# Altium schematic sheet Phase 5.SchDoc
size Tabloid; SheetNumber: 7; SheetTotal: 7
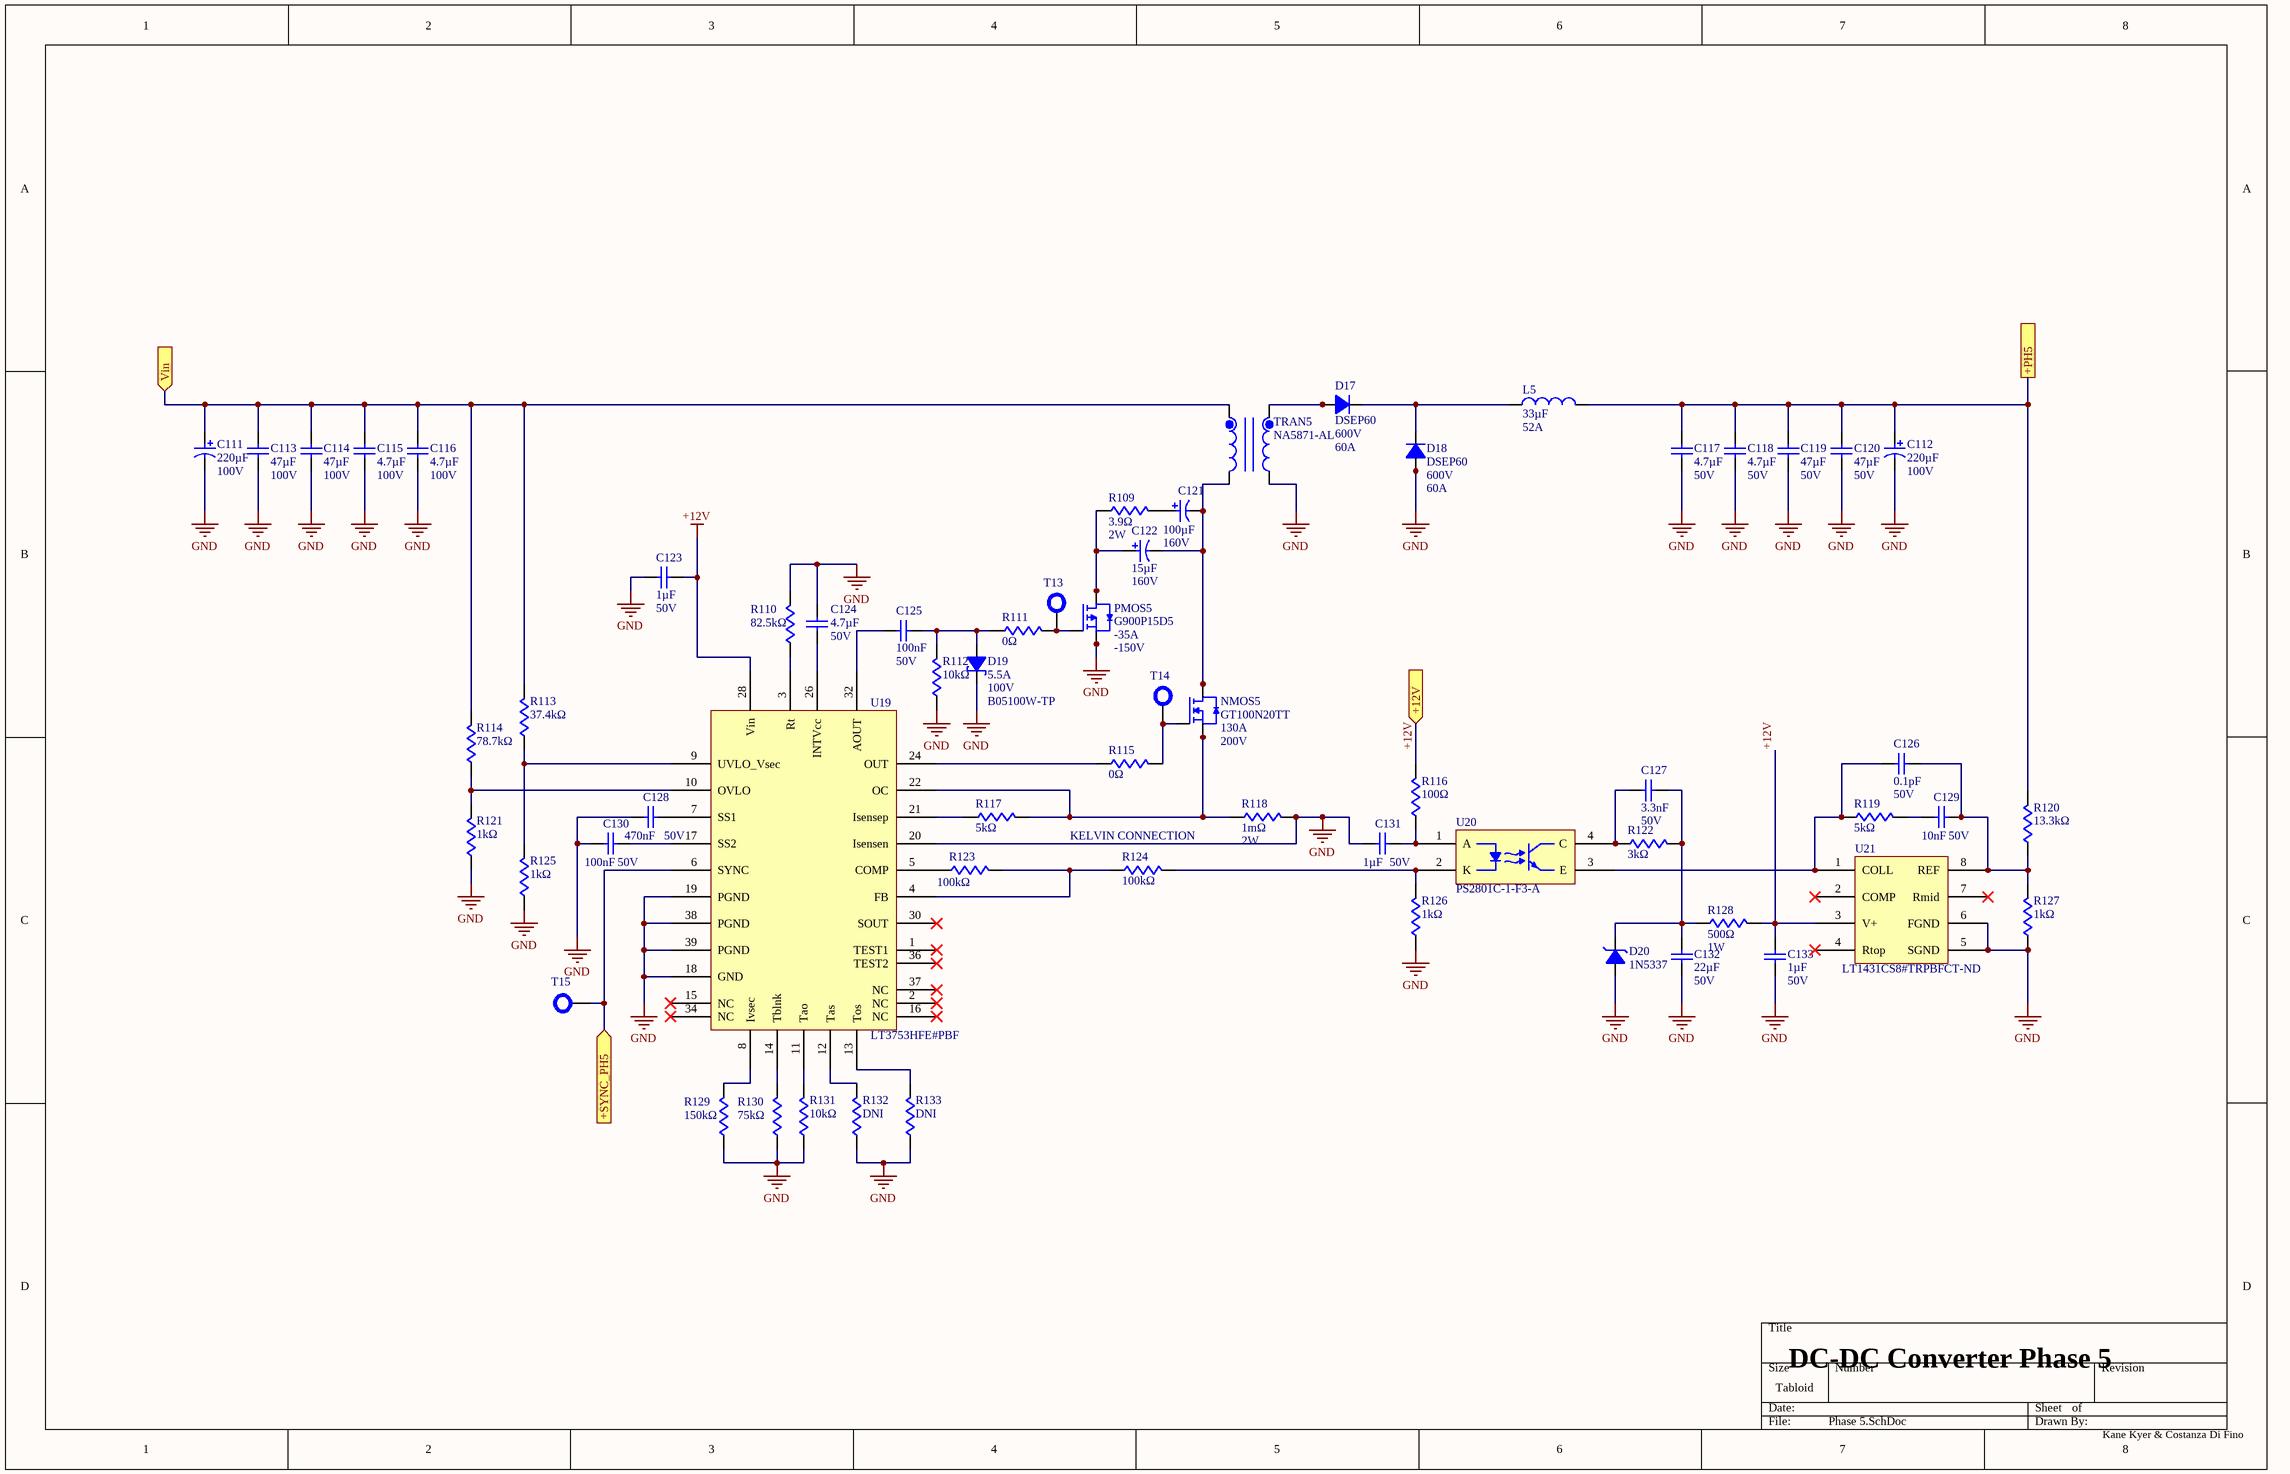
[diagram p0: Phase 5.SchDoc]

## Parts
C111  value 220µF  Voltage Rating: 100V  [C_AEC]  (hidden comment: AFK227M2AR44T-F)
C112  value 220µF  Voltage Rating: 100V  [C_AEC]  (hidden comment: AFK227M2AR44T-F)
C113  value 47µF  Voltage Rating: 100V  [C_CAA573]  (hidden comment: CAA573X7S2A476M640LH)
C114  value 47µF  Voltage Rating: 100V  [C_CAA573]  (hidden comment: CAA573X7S2A476M640LH)
C115  value 4.7µF  Voltage Rating (DC): 100V  [C_1210]  (hidden comment: GMC32X7S475K100NT)
C116  value 4.7µF  Voltage Rating (DC): 100V  [C_1210]  (hidden comment: GMC32X7S475K100NT)
C117  value 4.7µF  Voltage Rating (DC): 50V  [C_1206]  (hidden comment: GMC31X7R475K50NT)
C118  value 4.7µF  Voltage Rating (DC): 50V  [C_1206]  (hidden comment: GMC31X7R475K50NT)
C119  value 47µF  Voltage Rating (DC): 50V  [C_CKG57N]  (hidden comment: CKG57NX7R1H476M500JJ)
C120  value 47µF  Voltage Rating (DC): 50V  [C_CKG57N]  (hidden comment: CKG57NX7R1H476M500JJ)
C121  value 100µF  Voltage Rating (DC): 160V  [UUJ2C101MNJ1MS]  (hidden comment: UUJ2C101MNJ1MS)
C122  value 15µF  Voltage: 160V  [ULT2C150MNL1GS]  (hidden comment: ULT2C150MNL1GS)
C123  value 1µF  Voltage: 50V  [C_0805]  (hidden comment: CL21B105KBFNNNE)
C124  value 4.7µF  Voltage Rating (DC): 50V  [C_1206]  (hidden comment: GMC31X7R475K50NT)
C125  value 100nF  Voltage Rating: 50V  [C_0603]  (hidden comment: C0603C104K5RACTU)
C126  value 0.1pF  Voltage Rating: 50V  [C_0402]  (hidden comment: GJM1555C1HR10WB01D)
C127  value 3.3nF  Voltage Rating: 50V  [C_0603]  (hidden comment: GCM1885C1H332FA16D)
C128  value 470nF  Voltage Rating: 50V  [C_0402]  (hidden comment: GRM155R61H474KE11D)
C129  value 10nF  Voltage Rating: 50V  [C_0603]  (hidden comment: C0603C103K5RACTU)
C130  value 100nF  Voltage Rating: 50V  [C_0603]  (hidden comment: C0603C104K5RACTU)
C131  value 1µF  Voltage: 50V  [C_0805]  (hidden comment: CL21B105KBFNNNE)
C132  value 22µF  Voltage Rating (DC): 50V  [C_2220]  (hidden comment: GMC55X7R226M50NT)
C133  value 1µF  Voltage: 50V  [C_0805]  (hidden comment: CL21B105KBFNNNE)
D17  DSEP60  Vr: 600V  Io: 60A  [D_DSEP60]
D18  DSEP60  Vr: 600V  Io: 60A  [D_DSEP60]
D19  Max Forward Surge Current (Ifsm): 5.5A  Min Breakdown Voltage: 100V  [D_B05100W]  (hidden comment: B05100W-TP)
D20  Supplier Part Number: 1N5337  [D_1N5337]  (hidden comment: 1N5337BRLG)
L5  value 33µF  Irms: 52A  [CPEX4141L-330MC]  (hidden comment: CPEX4141L-330MC)
NMOS5  Id: 130A  Vds: 200V  [GT100N20TT]  (hidden comment: GT100N20TT)
PMOS5  Id: -35A  Vds: -150V  [G900P15]  (hidden comment: G900P15D5)
R109  value 3.9Ω  Power Rating: 2W  [R_SM2W]  (hidden comment: SMW23R9JT)
R110  value 82.5kΩ  [R_0805]  (hidden comment: RMCF0805FT82K5)
R111  value 0Ω  [R_0805]  (hidden comment: CRCW08050000Z0EA)
R112  value 10kΩ  [R_0402]  (hidden comment: RM04F1002CT)
R113  value 37.4kΩ  [R_0603]  (hidden comment: RC0603FR-0737K4L)
R114  value 78.7kΩ  [R_0603]  (hidden comment: RC0603FR-0778K7L)
R115  value 0Ω  [R_0805]  (hidden comment: CRCW08050000Z0EA)
R116  value 100Ω  [R_0603]  (hidden comment: RC0603FR-07100RL)
R117  value 5kΩ  [R_0402]  (hidden comment: PNM0402E5001BST1)
R118  value 1mΩ  Power Rating: 2W  [R_2512]  (hidden comment: CRE2512-FZ-R001E-2)
R119  value 5kΩ  [R_0402]  (hidden comment: PNM0402E5001BST1)
R120  value 13.3kΩ  [R_0603]  (hidden comment: RMCF0603FT13K3)
R121  value 1kΩ  [R_0402]  (hidden comment: RM04F1001CT)
R122  value 3kΩ  [C_0402]  (hidden comment: AC0402FR-073KL)
R123  value 100kΩ  [R_0402]  (hidden comment: RM04F1003CT)
R124  value 100kΩ  [R_0402]  (hidden comment: RM04F1003CT)
R125  value 1kΩ  [R_0402]  (hidden comment: RM04F1001CT)
R126  value 1kΩ  [R_0402]  (hidden comment: RM04F1001CT)
R127  value 1kΩ  [R_0402]  (hidden comment: RM04F1001CT)
R128  value 500Ω  Power Rating: 1W  [R_WSC2515]  (hidden comment: WSC2515500R0FEB)
R129  value 150kΩ  [R_0603]  (hidden comment: RC0603FR-07150KL)
R130  value 75kΩ  [R_0603]  (hidden comment: AC0603FR-0775KL)
R131  value 10kΩ  [R_0402]  (hidden comment: RM04F1002CT)
R132  value DNI  [R_0805]  (hidden comment: CRCW08050000Z0EA)
R133  value DNI  [R_0805]  (hidden comment: CRCW08050000Z0EA)
T13  TEST  [TEST_POINT]  (value not drawn)
T14  TEST  [TEST_POINT]  (value not drawn)
T15  TEST  [TEST_POINT]  (value not drawn)
TRAN5  NA5871-AL  [NA5871-AL]
U19  LT3753HFE#PBF  [LT3753]
U20  PS2801C-1-F3-A  [PS2801C]
U21  Supplier Part Number: LT1431CS8#TRPBFCT-ND  [LT1431]  (hidden comment: LT1431CS8#TRPBF)

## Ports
+12V (in, see SHEET_MAP[4C], Externals[2A], Phase 1[4C], Phase 2[4C], Phase 3[4C], Phase 4[4C]), +PH5 (see SHEET_MAP[4C], Externals[6C], Phase 4[6C]), +SYNC_PH5 (in, see SHEET_MAP[4C], Externals[3C]), Vin (in, see SHEET_MAP[4C], Externals[1A], Phase 1[1B], Phase 2[1B], Phase 3[1B], Phase 4[1B])

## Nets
+12V: C123.2 C133.2 R116.2 R128.2 U19.28(Vin) U21.3(V+) ; port +12V
GND: C111.2 C112.2 C113.1 C114.1 C115.1 C116.1 C117.1 C118.1 C119.1 C120.1 C123.1 C124.1 C128.1 C130.1 C131.1 C132.1 C133.1 D18.1(A) D18.3(A) D19.1 D20.2 PMOS5.1(S) PMOS5.2(S) PMOS5.3(S) R110.2 R112.1 R118.2 R121.1 R125.1 R126.1 R127.1 R129.1 R130.1 R131.1 R132.1 R133.1 TRAN5.11 U19.18(GND) U19.19(PGND) U19.20(Isensen) U19.38(PGND) U19.39(PGND) U21.5(SGND) U21.6(FGND)
+PH5: C112.1 C117.2 C118.2 C119.2 C120.2 L5.2 R120.2 ; port +PH5
+SYNC_PH5: T15.1 U19.6(SYNC) ; port +SYNC_PH5
Vin: C111.1 C113.2 C114.2 C115.2 C116.2 R113.2 R114.2 TRAN5.1 ; port Vin
NetC121_1: C121.1 R109.2
NetC121_2: C121.2 C122.2 NMOS5.9(D) NMOS5.10(D) NMOS5.11(D) NMOS5.12(D) NMOS5.13(D) NMOS5.14(D) NMOS5.15(D) NMOS5.16(D) TRAN5.4
NetC122_1: C122.1 PMOS5.5(D) PMOS5.6(D) PMOS5.7(D) PMOS5.8(D) R109.1
NetC124_2: C124.2 U19.26(INTVcc)
NetC125_1: C125.1 U19.32(AOUT)
NetC125_2: C125.2 D19.2 R111.1 R112.2
NetC126_1: C126.1 R119.1 U20.3(E) U21.1(COLL)
NetC126_2: C126.2 C129.2 R120.1 R127.2 U21.8(REF)
NetC127_1: C127.1 R122.1 U20.4(C)
NetC127_2: C127.2 C132.2 D20.1 R122.2 R128.1
NetC128_2: C128.2 U19.7(SS1)
NetC129_1: C129.1 R119.2
NetC130_2: C130.2 U19.17(SS2)
NetC131_2: C131.2 R116.1 U20.1(A)
NetD17_1: D17.1(A) D17.3(A) TRAN5.6
NetD17_4: D17.4(C) D18.4(C) L5.1
NetNMOS5_1: NMOS5.1(S) NMOS5.2(S) NMOS5.3(S) NMOS5.4(S) NMOS5.5(S) NMOS5.6(S) NMOS5.7(S) R117.2 R118.1 U19.22(OC)
NetNMOS5_8: NMOS5.8(G) R115.2 T14.1
NetPMOS5_4: PMOS5.4(G) R111.2 T13.1
NetR110_1: R110.1 U19.3(Rt)
NetR113_1: R113.1 R125.2 U19.9(UVLO_Vsec)
NetR114_1: R114.1 R121.2 U19.10(OVLO)
NetR115_1: R115.1 U19.24(OUT)
NetR117_1: R117.1 U19.21(Isensep)
NetR123_1: R123.1 U19.5(COMP)
NetR123_2: R123.2 R124.1 U19.4(FB)
NetR124_2: R124.2 R126.2 U20.2(K)
NetR129_2: R129.2 U19.8(Ivsec)
NetR130_2: R130.2 U19.14(Tblnk)
NetR131_2: R131.2 U19.11(Tao)
NetR132_2: R132.2 U19.12(Tas)
NetR133_2: R133.2 U19.13(Tos)

Not connected (* = marked no-connect by the designer): U19 1(TEST1)* 2(NC)* 15(NC)* 16(NC)* 30(SOUT)* 34(NC)* 36(TEST2)* 37(NC)*; U21 2(COMP)* 4(Rtop)* 7(Rmid)*

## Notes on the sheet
- (near R124) KELVIN CONNECTION
- DC-DC Converter Phase 5
- Kane Kyer & Costanza Di Fino

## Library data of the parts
C111 C112 = AFK227M2AR44T-F: Radial Can - SMD ALUMINUM ELECTROLYTIC CAPACITOR AFK 100V 220muF ±20% 0.709Dia 18.00mm; Manufacturer: Cornell Dubilier; Dissipation Factor: 0.07%; ESR (Equivalent Series Resistance): 150mΩ; Leakage Current: 220µA; Life (Hours): 5000hours; Ripple Current: 687.75mA; Ripple Current (AC): 917mA
C113 C114 = CAA573X7S2A476M640LH: Multilayer Ceramic Chip Capacitors, Capacitance=47μF, LxWxT: 6.0x7.5x6.4mm; Manufacturer: TDK; Manufacturer Lifecycle Status: PRODUCTION; Tolerance: 20%
C115 C116 = GMC32X7S475K100NT: Ceramic Capacitor, Multilayer, Ceramic, 100V, 10% +Tol, 10% -Tol, X7S, 22% TC, 4.7uF, Surface Mount, 1210; Manufacturer: Cal-Chip Electronics
C117 C118 C124 = GMC31X7R475K50NT: Ceramic Capacitor, Multilayer, Ceramic, 50V, 10% +Tol, 10% -Tol, X7R, 15% TC, 4.7uF, Surface Mount, 1206; Manufacturer: Cal-Chip Electronics
C119 C120 = CKG57NX7R1H476M500JJ: Ceramic Capacitor, Multilayer, Ceramic, 50V, 20% +Tol, 20% -Tol, X7R, 15% TC, 47uF, Surface Mount, 2420; Manufacturer: TDK; Manufacturer Lifecycle Status: PRODUCTION
C121 = UUJ2C101MNJ1MS: Aluminum Electrolytic Capacitors 100 F 160 V Radial, SMD 5000 Hrs 105C; Manufacturer: Nichicon; Leakage Current: 740µA; Ripple Current: 380mA
C122 = ULT2C150MNL1GS: Radial Can - SMD ALUMINUM ELECTROLYTIC CAPACITOR ULT 160V 15muF ±20% 0.315Dia 8.00mm; Manufacturer: Nichicon; Leakage Current: 196µA; Life (Hours): 2000hours; Polarity: Polar; Ripple Current: 45mA
C123 C131 C133 = CL21B105KBFNNNE: 50V 1uF X7R ±10% 0805 Multilayer Ceramic Capacitors MLCC - SMD/SMT ROHS; Manufacturer: Samsung Electro-Mechanics
C125 C130 = C0603C104K5RACTU: 50V 100nF X7R ±10% 0603 Multilayer Ceramic Capacitors MLCC - SMD/SMT ROHS; Manufacturer: KEMET; Dissipation Factor: 2.5%; Temperature Coefficient: 30ppm/°C
C126 = GJM1555C1HR10WB01D: Multilayer Ceramic Capacitor, 0.1 pF, 50 V, ± 0.05pF, C0G (NP0), 0402 [1005 Metric]; Manufacturer: Murata; Manufacturer Lifecycle Status: IN PRODUCTION; Temperature Coefficient: 30ppm/°C
C127 = GCM1885C1H332FA16D: 50V 3.3nF C0G ±1% 0603 Multilayer Ceramic Capacitors MLCC - SMD/SMT ROHS; Manufacturer: Murata; Manufacturer Lifecycle Status: IN PRODUCTION; Temperature Coefficient: 30ppm/°C
C128 = GRM155R61H474KE11D: 50V 470nF X5R ±10% 0402 Multilayer Ceramic Capacitors MLCC - SMD/SMT ROHS; Manufacturer: Murata; Manufacturer Lifecycle Status: IN PRODUCTION
C129 = C0603C103K5RACTU: Capacitor, Multilayer, Ceramic, 50V, 10%, X7R, 15% Tc, 0.01Uf, Surface Mount, 0603; Manufacturer: KEMET; Dissipation Factor: 2.5%; Temperature Coefficient: 30ppm/°C
C132 = GMC55X7R226M50NT: Ceramic Capacitor, Multilayer, Ceramic, 50V, 20% +Tol, 20% -Tol, X7R, 15% TC, 22uF, Surface Mount, 2220; Manufacturer: Cal-Chip Electronics
D17 D18 = DSEP60-06AZ-TRL: Power Diode Discretes-FRED TO-; Manufacturer: IXYS
D19 = B05100W-TP: Rectifier Diode, Schottky, 1 Phase, 1 Element, 0.5A, 100V V(RRM), Silicon; Manufacturer: MCC; Forward Voltage: 850mV; Max Output current: 500mA; Number of Elements: 1; Peak Reverse Current: 1µA
D20 = 1N5337BRLG: Zener Diode Single 4.7V 5% 2Ohm 5000mW 2-Pin Case 017AA-01 T/R / DIODE ZENER 4.7V 5W AXIAL; Manufacturer: onsemi; Manufacturer Lifecycle Status: ACTIVE; Forward Voltage: 1.2V; Impedance: 2Ω; Max Reverse Leakage Current: 5µA; Number of Elements: 1; Polarity: Unidirectional; Test Current: 260mA
L5 = CPEX4141L-330MC: Fixed Ind 33UH 52A 1.88 Mohm Th; Manufacturer: Codaca
NMOS5 = GT100N20TT: Mosfet N-ch 200V 130A 280W Tolt; Manufacturer: GoFord
PMOS5 = G900P15D5: P-150V, -60A, RD(max) Less Than 80mOhm at -10V, VTH -1V to -4V, DFN5x6-8L; Manufacturer: GoFord; Manufacturer Lifecycle Status: ACTIVE
R109 = SMW23R9JT: SM Series 3.9 Ohm ±5 % 2 W ±200 ppm/°C Surface Mount Wirewound Resistor; Manufacturer: TE Connectivity; Manufacturer Lifecycle Status: ACTIVE; Insulation Resistance: 10GΩ; Number of Resistors: 1; Operating Supply Voltage: 300V; Tolerance: 5%
R110 = RMCF0805FT82K5: Res Thick Film 0805 82.5K Ohm 1% 1/8W ±100ppm/°C Molded SMD SMD Paper T/R; Manufacturer: Stackpole Electronics; Max Power Dissipation: 125mW; Voltage Rating: 150V
R111 R115 R132 R133 = CRCW08050000Z0EA: Zero Ohm Resistor, Jumper, 0805 [2012 Metric], Thick Film, 125 mW, 2.5 A, Surface Mount Device; Manufacturer: Vishay; Manufacturer Package Identifier: CRCW0805-e3; Power Dissipation: 125mW; Temperature Coefficient: 100ppm/°C; Tolerance: 1%; Voltage Rating: 150V
R112 R131 = RM04F1002CT: Fixed Resistor, Metal Glaze/thick Film, 0.0625W, 10000ohm, 50V, 1% +/-Tol, Surface Mount, 0402; Manufacturer: Cal-Chip Electronics; Power Dissipation: 62.5mW; Power Rating: 63mW; Temperature Coefficient: 100ppm/°C
R113 = RC0603FR-0737K4L: 100mW Thick Film Resistors 75V ±100ppm/℃ ±1% 37.4kΩ 0603 Chip Resistor - Surface Mount ROHS; Manufacturer: Yageo Group; Temperature Coefficient: 100ppm/°C; Voltage Rating (DC): 50V
R114 = RC0603FR-0778K7L: Res Thick Film 0603 78.7K Ohm 1% 0.1W(1/10W) ±100ppm/C Pad SMD T/R; Manufacturer: Yageo Group; Power Dissipation: 100mW; Temperature Coefficient: 100ppm/°C; Voltage Rating: 75V; Voltage Rating (DC): 50V
R116 = RC0603FR-07100RL: Yageo RC0603FR-07100RL 0603 SMD Resistor 100 Ohm thin film chip resistor; Manufacturer: Yageo Group; Power Dissipation: 100mW; Temperature Coefficient: 100ppm/°C; Tolerance: 1%; Voltage Rating: 75V; Voltage Rating (DC): 50V
R117 R119 = PNM0402E5001BST1: Res Thin Film 0402 5K Ohm 0.1% 0.05W(1/20W) +/-25ppm/C Sulfur Resistant Pad SMD Medical T/R; Manufacturer: Vishay; Power Dissipation: 50mW; Temperature Coefficient: 25ppm/°C; Working Voltage: 75V
R118 = CRE2512-FZ-R001E-2: Res Thick Film 2512 1m Ohm 1% 2W ±75ppm/°C Molded SMD Embossed T/R; Manufacturer: Bourns; Temperature Coefficient: 50ppm/°C
R120 = RMCF0603FT13K3: Res Thick Film 0603 13.3K Ohm 1% 0.1W(1/10W) ±100ppm/C Pad SMD Automotive T/R; Manufacturer: Stackpole Electronics; Power Dissipation: 100mW; Temperature Coefficient: 100ppm/°C; Voltage Rating: 75V
R121 R125-R127 = RM04F1001CT: 62.5mW Thick Film Resistors ±100ppm/℃ ±1% 1kΩ 0402 Chip Resistor - Surface Mount ROHS; Manufacturer: Cal-Chip Electronics; Temperature Coefficient: 100ppm/°C; Working Voltage: 50V
R122 = AC0402FR-073KL: Res Thick Film 0402 3K Ohm 1% 0.063W(1/16W) ±100ppm/C Pad SMD Automotive T/R; Manufacturer: Yageo Group; Max Power Dissipation: 63mW; Power Dissipation: 62.5mW; Temperature Coefficient: 100ppm/°C; Voltage Rating: 50V
R123 R124 = RM04F1003CT: Fixed Resistor, Metal Glaze/thick Film, 0.0625W, 100000ohm, 50V, 1% +/-Tol, Surface Mount, 0402; Manufacturer: Cal-Chip Electronics; Power Dissipation: 62.5mW; Temperature Coefficient: 100ppm/°C
R128 = WSC2515500R0FEB: Fixed Resistor, Wire Wound, 1W, 500ohm, 22.3607V, 1% +/-Tol, 20ppm/Cel, Surface Mount, 2515; Manufacturer: Vishay; Temperature Coefficient: 20ppm/°C
R129 = RC0603FR-07150KL: 100mW Thick Film Resistors 75V ±100ppm/℃ ±1% 150kΩ 0603 Chip Resistor - Surface Mount ROHS; Manufacturer: Yageo Group; Temperature Coefficient: 100ppm/°C; Voltage Rating (AC): 50V
R130 = AC0603FR-0775KL: Res Thick Film 0603 75K Ohm 1% 0.1W(1/10W) ±100ppm/C Pad SMD T/R Automotive AEC-Q200; Manufacturer: Yageo Group; Max Power Dissipation: 100mW; Temperature Coefficient: 100ppm/°C; Voltage Rating: 75V
TRAN5 = NA5871-AL: Transformer, planar, for TI UCC28950, SMT, RoHS; Manufacturer: Coilcraft; Max Supply Voltage: 60V; Min Input Voltage: 38V; Power Rating: 800W
U19 = LT3753HFE#PBF: 500kHz 8.5V~100V Buck-boost type 1 TSSOP-38-EP-4.4mm DC-DC Controllers ROHS; Manufacturer: Analog Devices; Manufacturer Lifecycle Status: PRODUCTION; Clock Sync: Yes; Max Supply Voltage: 100V; Min Supply Voltage: 8.5V; Nominal Supply Voltage: 12V; Number of Output Phases: 1; Topology: Forward Converter
U20 = PS2801C-1-F3-A: Optocoupler DC-IN 1-CH Transistor DC-OUT 4-Pin SSOP T/R; Manufacturer: Renesas; Manufacturer Lifecycle Status: ACTIVE; Collector Emitter Breakdown Voltage: 80V; Collector Emitter Saturation Voltage: 300mV; Current Transfer Ratio: 50%; Dark Current: 100nA; Forward Current: 30mA; Forward Voltage: 1.4V; Input Current: 5mA; Isolation Voltage: 2.5kV; Max Power Dissipation: 120mW; Number of Elements: 1; Reverse Breakdown Voltage: 6V; Target Application: PLC\, Hybrid IC\, Power supply\, OA\, Measuring instrument\, Modem\, Communication devices
U21 = LT1431CS8#TRPBF: V-Ref Adjustable 2.5V to 36V 100mA 8-Pin SOIC N T/R; Manufacturer: Analog Devices; Manufacturer Lifecycle Status: PRODUCTION; Cathode Current: 1mA; Reference Type: Shunt; Temperature Coefficient: 30ppm/°C; Tolerance: 0.4%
